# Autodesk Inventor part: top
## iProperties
Created: 2005-05
Part Number: top
Material: cherry
Document SubType Name: Modeling
Designer: a.campbell
Manufacturer: Standard
Standards Organization: Custom
length: 350
thickness: 19
width: 442
Author: a.campbell
Comments: machine to detail
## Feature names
1. Extrusion1
2. Extrusion2
